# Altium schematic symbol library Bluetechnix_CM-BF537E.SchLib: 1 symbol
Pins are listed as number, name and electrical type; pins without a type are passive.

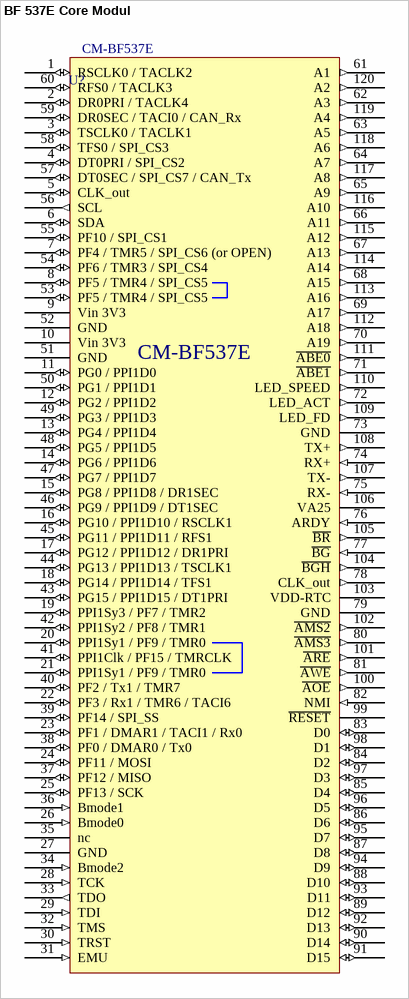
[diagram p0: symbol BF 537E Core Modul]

## BF 537E Core Modul
designator U?, comment CM-BF537E
Bluetechnix CM-BF537E
pins: 1 RSCLK0 / TACLK2 (io), 2 DR0PRI / TACLK4 (io), 3 TSCLK0 / TACLK1 (io), 4 DT0PRI / SPI_CS2 (io), 5 CLK_out (io), 6 SDA (io), 7 PF4 / TMR5 / SPI_CS6 (or OPEN) (io), 8 PF5 / TMR4 / SPI_CS5 (io), 9 Vin 3V3 (power), 10 Vin 3V3 (power), 11 PG0 / PPI1D0 (io), 12 PG2 / PPI1D2 (io), 13 PG4 / PPI1D4 (io), 14 PG6 / PPI1D6 (io), 15 PG8 / PPI1D8 / DR1SEC (io), 16 PG10 / PPI1D10 / RSCLK1 (io), 17 PG12 / PPI1D12 / DR1PRI (io), 18 PG14 / PPI1D14 / TFS1 (io), 19 PPI1Sy3 / PF7 / TMR2 (io), 20 PPI1Sy1 / PF9 / TMR0 (io), 21 PPI1Sy1 / PF9 / TMR0 (io), 22 PF3 / Rx1 / TMR6 / TACI6 (io), 23 PF1 / DMAR1 / TACI1 / Rx0 (io), 24 PF11 / MOSI (io), 25 PF13 / SCK (io), 26 Bmode0 (in), 27 GND (power), 28 TCK (in), 29 TDI (in), 30 TRST (in), 31 EMU (in), 32 TMS (in), 33 TDO (out), 34 Bmode2 (in), 35 nc (power), 36 Bmode1 (in), 37 PF12 / MISO (io), 38 PF0 / DMAR0 / Tx0 (io), 39 PF14 / SPI_SS (io), 40 PF2 / Tx1 / TMR7 (io), 41 PPI1Clk / PF15 / TMRCLK (io), 42 PPI1Sy2 / PF8 / TMR1 (io), 43 PG15 / PPI1D15 / DT1PRI (io), 44 PG13 / PPI1D13 / TSCLK1 (io), 45 PG11 / PPI1D11 / RFS1 (io), 46 PG9 / PPI1D9 / DT1SEC (io), 47 PG7 / PPI1D7 (io), 48 PG5 / PPI1D5 (io), 49 PG3 / PPI1D3 (io), 50 PG1 / PPI1D1 (io), 51 GND (power), 52 GND (power), 53 PF5 / TMR4 / SPI_CS5 (io), 54 PF6 / TMR3 / SPI_CS4 (io), 55 PF10 / SPI_CS1 (io), 56 SCL (out), 57 DT0SEC / SPI_CS7 / CAN_Tx (io), 58 TFS0 / SPI_CS3 (io), 59 DR0SEC / TACI0 / CAN_Rx (io), 60 RFS0 / TACLK3 (io), 61 A1 (out), 62 A3 (out), 63 A5 (out), 64 A7 (out), 65 A9 (out), 66 A11 (out), 67 A13 (out), 68 A15 (out), 69 A17 (out), 70 A19 (out), 71 ~{ABE1} (out), 72 LED_ACT (out), 73 GND (power), 74 RX+ (in), 75 RX- (in), 76 ARDY (in), 77 ~{BG} (in), 78 CLK_out (out), 79 GND (power), 80 ~{AMS3} (out), 81 ~{AWE} (out), 82 NMI (in), 83 D0 (io), 84 D2 (io), 85 D4 (io), 86 D6 (io), 87 D8 (io), 88 D10 (io), 89 D12 (io), 90 D14 (io), 91 D15 (io), 92 D13 (io), 93 D11 (io), 94 D9 (io), 95 D7 (io), 96 D5 (io), 97 D3 (io), 98 D1 (io), 99 ~{RESET}, 100 ~{AOE} (out), 101 ~{ARE} (out), 102 ~{AMS2} (out), 103 VDD-RTC (power), 104 ~{BGH} (out), 105 ~{BR} (out), 106 VA25 (power), 107 TX- (out), 108 TX+ (out), 109 LED_FD (out), 110 LED_SPEED (out), 111 ~{ABE0} (out), 112 A18 (out), 113 A16 (out), 114 A14 (out), 115 A12 (out), 116 A10 (out), 117 A8 (out), 118 A6 (out), 119 A4 (out), 120 A2 (out)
